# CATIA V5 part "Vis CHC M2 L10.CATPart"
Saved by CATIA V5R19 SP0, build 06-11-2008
Part number: Vis CHC M2 L10
Revision: ANY
Definition: UNKNOWN
Nomenclature: Vis CHC M2 L10
Source: Unknown
Bounding box of the stored display mesh (mm): x -1.899 to 1.899, y -49.29 to -37.29, z -1.9 to 1.9
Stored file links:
  C:\Users\Rémi\Documents\BTS CPI\Projet 04- Guitar Elec\Maquette\Vis CHC M2 L10.CATPart
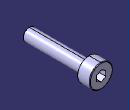
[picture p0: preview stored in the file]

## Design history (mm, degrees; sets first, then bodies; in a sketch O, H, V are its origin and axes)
Body1 "Enlèv. mat.-Extru.1" (main body)
  Solid1: solid without history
